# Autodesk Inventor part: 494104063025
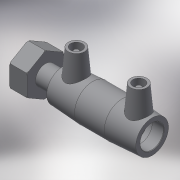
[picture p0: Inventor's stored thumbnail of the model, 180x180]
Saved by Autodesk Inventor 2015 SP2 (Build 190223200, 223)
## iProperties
Created: 2017-06
Part Number: 494104063025
Material: Generic
Description: PLASSON FEMALE FREE NUT TRANSITION COUPLER 63-2.1/2"
Document SubType Name: Modeling
Designer: KIM
Mass: 55.0731 g
Surface Area: 148.067 cm^2
Volume: 55.0731 cm^3
Density: 1 g/cm^3
Appearance: Default
Author: KIM
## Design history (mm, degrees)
derived "494104.ipt"
feature "Solid1::494104.ipt"
tag "TaggingFeature1"
body "Solid1"
other parameters: "d0" = 117, "d1" = 63, "d2" = 82, "d3" = 57, "d4" = 39, "d5" = 73.8, "d6" = 59.85, "d7" = 63, "d8" = 168 deg, "d10" = 22.8, "d11" = 7.6, "d29" = 57, "d30" = 14, "d31" = 40.95, "d34" = 5 deg, "d41" = 4, "d42" = 14, "d43" = 0, "d48" = 3, "d49" = 0, "d55" = 49, "d57" = 48, "d80" = 1.26, "d83" = 24.5, "d84" = 16.17, "d85" = 1.617, "d86" = 57.7808, "d87" = 72.226, "d88" = 108.339, "d89" = 82, "d90" = 2.16678, "d94" = 0, "d95" = 1.617, "d96" = 50.5582, "d_" = 63, "L_" = 166, "L_1" = 57, "D_1" = 82, "A_" = 57, "d_2" = 12, "L_2" = 49, "D_" = 48, "G_" = 72.226
